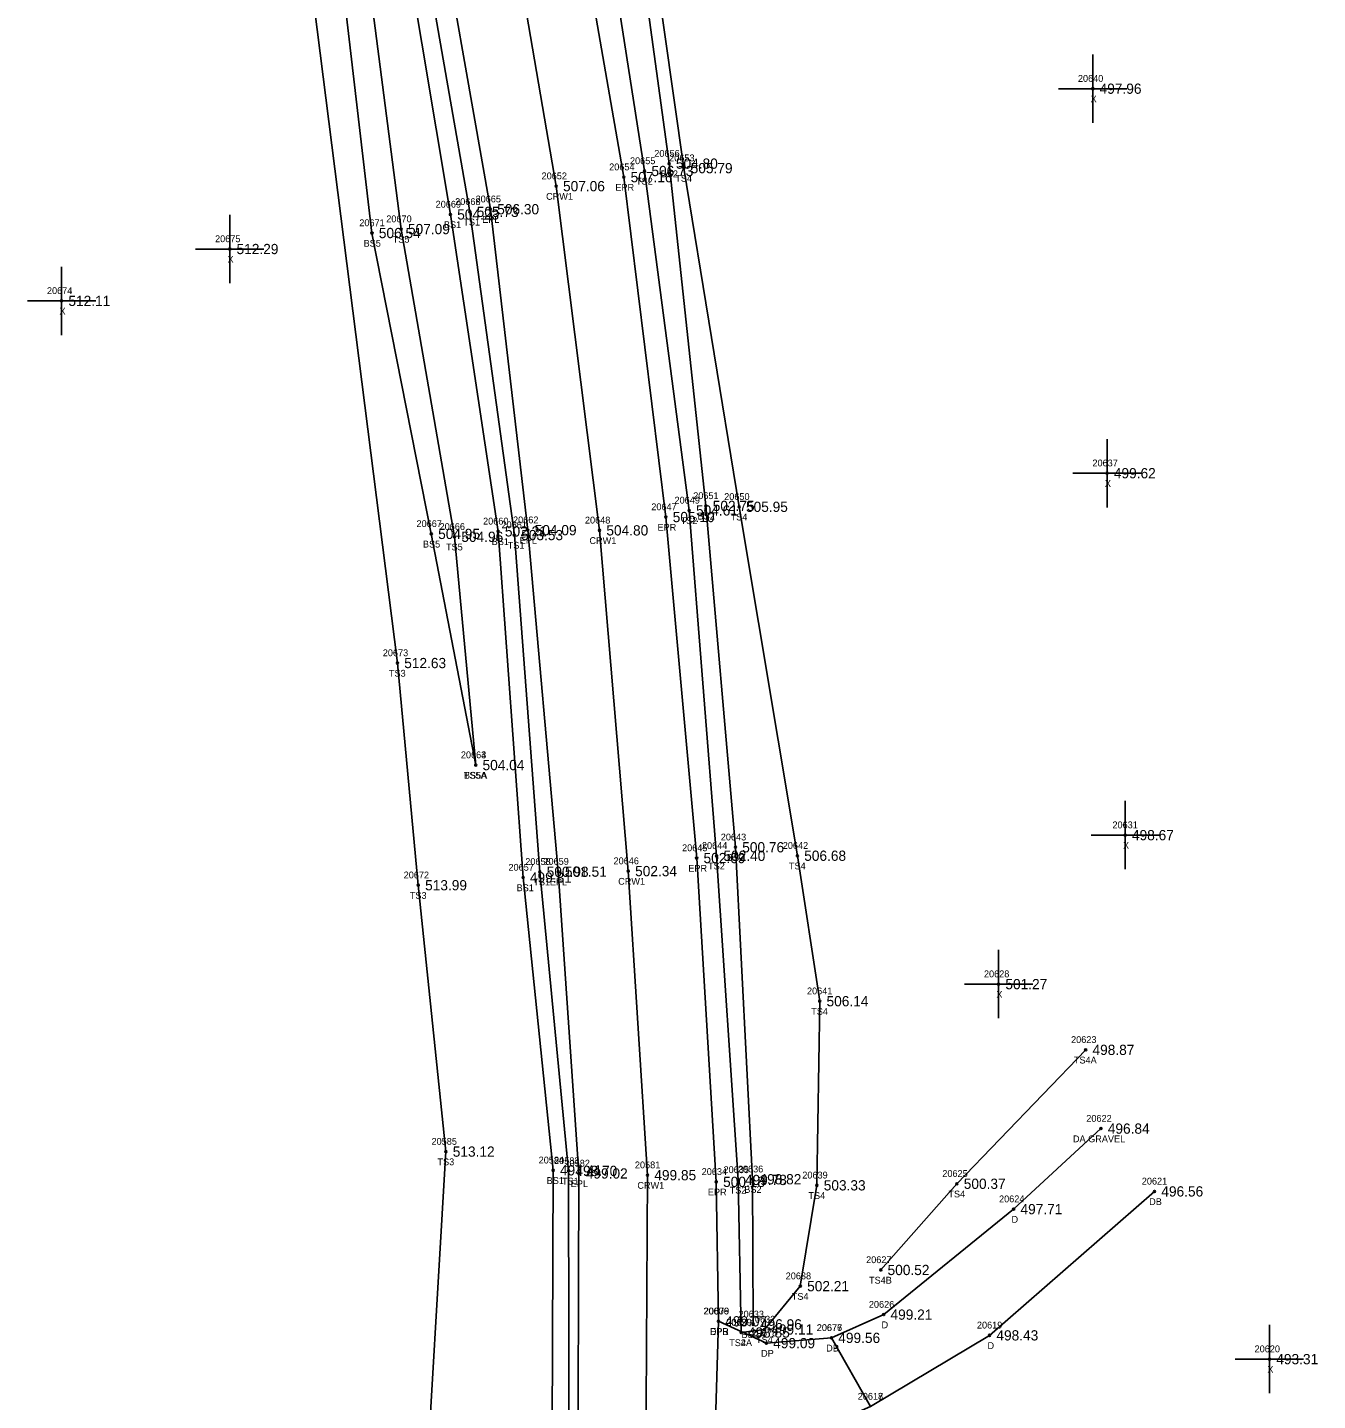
# Model space of a CAD drawing. Extents: x 1649406 to 1650436, y 896752 to 898178.
# Drawn here: x 1649854.4 to 1650043.4, y 897780.3 to 897981.4 of the extents above; entities that cross this region are included whole.
import ezdxf

# ---------------------------------------------------------------- set-up
doc = ezdxf.new("R2010")
doc.units = 0
for name, color, linetype in [('RD_DTM_BkLn1', 7, 'Continuous'), ('RD_DTM_BkLn2', 7, 'Continuous'), ('RD_DTM_BkLn_txCode', 7, 'Continuous'), ('RD_EX_Driveway', 7, 'Continuous'), ('RD_EX_Driveway_txCode', 7, 'Continuous'), ('RD_EX_Misc', 7, 'Continuous'), ('RD_EX_Misc_txCode', 7, 'Continuous'), ('RD_EX_Road', 7, 'Continuous'), ('RD_EX_Road_txCode', 7, 'Continuous'), ('RD_EX_TX_Driveway_ELEV', 7, 'Continuous'), ('RD_EX_TX_Misc_ELEV', 7, 'Continuous'), ('RD_EX_TX_Road_ELEV', 7, 'Continuous'), ('RD_HC_Survey_ELEV', 7, 'Continuous'), ('RD_HC_Survey_txCode', 7, 'Continuous'), ('RD_SMD_Locator', 7, 'Continuous')]:
    doc.layers.add(name, color=color, linetype=linetype)

msp = doc.modelspace()

# ---------------------------------------------------------------- linework, layer by layer
at = {"layer": 'RD_DTM_BkLn1'}
msp.add_lwpolyline([(1649894.9, 897462.66), (1649908.82, 897514.7), (1649920.62, 897564.87), (1649930.21, 897614.13), (1649937.18, 897663.59), (1649942.29, 897713.83), (1649944.94, 897762.9), (1649945.25, 897813.29), (1649942.44, 897857.84), (1649938.23, 897907.76), (1649931.88, 897958.19), (1649923.51, 898006.94), (1649914.47, 898059.31), (1649904.54, 898110.23), (1649895.09, 898157.93)], dxfattribs=at)
at = {"layer": 'RD_DTM_BkLn2'}
for points in [[(1649960.73, 897791.43), (1649960.66, 897812.69), (1649958.13, 897861.33), (1649953.81, 897911.34), (1649948.42, 897961.49), (1649941.65, 898011.04), (1649931.14, 898062.52), (1649921.88, 898114.25), (1649913.27, 898162.17)], [(1649958.96, 897790.24), (1649962.39, 897790.68), (1649967.64, 897797.03), (1649970.07, 897811.8), (1649970.48, 897838.78), (1649967.21, 897860.09), (1649958.68, 897911.21), (1649950.58, 897960.83), (1649943.4, 898011.37), (1649933.69, 898063.19), (1649926.67, 898115.06), (1649916.83, 898162.27)], [(1649958.96, 897790.24), (1649958.53, 897812.59), (1649955.38, 897860.08), (1649951.36, 897910.68), (1649944.83, 897960.41), (1649937.13, 898009.63), (1649927.84, 898061.63), (1649917.14, 898113.1), (1649909.51, 898160.93)], [(1649920.87, 897644.21), (1649923.9, 897665.21), (1649928.63, 897702.34), (1649930.33, 897715.28), (1649933.79, 897763.23), (1649933.69, 897813.91), (1649929.49, 897857.74), (1649925.75, 897907.07), (1649919.24, 897954.42), (1649910.51, 898004.53), (1649900.99, 898055.57), (1649897.4, 898076.37), (1649890.54, 898075.59)], [(1649920.09, 897873.37), (1649916.99, 897906.82), (1649909.17, 897951.9), (1649902.46, 898003.64), (1649895.01, 898054.19), (1649890.54, 898075.59)], [(1649902.31, 897569.09), (1649911.24, 897617.29), (1649920.65, 897666.08), (1649926.58, 897702.16), (1649928.32, 897715.46), (1649931.24, 897763.41), (1649931.43, 897814), (1649927.03, 897856.89), (1649923.37, 897907.61), (1649916.38, 897954.04), (1649907.99, 898004.31), (1649897.74, 898054.92), (1649893.88, 898075.41)], [(1649920.09, 897873.37), (1649913.59, 897907.24), (1649904.9, 897951.32), (1649898.8, 898003.15), (1649890.21, 898053.37), (1649884.63, 898071.42)], [(1649868.11, 897593.32), (1649891.92, 897625.99), (1649904.5, 897665.19), (1649913.68, 897716.44), (1649912.45, 897760.99), (1649915.73, 897816.74), (1649911.68, 897855.77), (1649908.62, 897888.32), (1649894.21, 898001.99), (1649884.42, 898052.27), (1649879.49, 898066.69)], [(1650009.44, 897831.65), (1649990.58, 897812.03), (1649979.42, 897799.4)]]:
    msp.add_lwpolyline(points, dxfattribs=at)
at = {"layer": 'RD_EX_Driveway'}
for points in [[(1650011.68, 897820.11), (1649998.89, 897808.31), (1649979.85, 897792.86), (1649972.2, 897789.45)], [(1649977.91, 897779.39), (1649995.36, 897789.82), (1650019.52, 897810.91)], [(1649954.77, 897762.63), (1649957.88, 897765.34), (1649960.78, 897770.05), (1649964.93, 897773.68), (1649977.91, 897779.39), (1649972.2, 897789.45), (1649962.67, 897788.68), (1649955.64, 897791.88)]]:
    msp.add_lwpolyline(points, dxfattribs=at)
at = {"layer": 'RD_EX_Misc'}
for p, q in [((1650010.48, 897967.47), (1650010.48, 897977.47)), ((1650005.48, 897972.47), (1650015.48, 897972.47)), ((1649884.06, 897943.98), (1649884.06, 897953.98)), ((1649879.06, 897948.98), (1649889.06, 897948.98)), ((1649859.43, 897936.38), (1649859.43, 897946.38)), ((1649854.43, 897941.38), (1649864.43, 897941.38)), ((1650012.57, 897911.13), (1650012.57, 897921.13)), ((1650007.57, 897916.13), (1650017.57, 897916.13)), ((1650015.22, 897858.11), (1650015.22, 897868.11)), ((1650010.22, 897863.11), (1650020.22, 897863.11)), ((1649996.68, 897836.28), (1649996.68, 897846.28)), ((1649991.68, 897841.28), (1650001.68, 897841.28)), ((1650036.36, 897781.34), (1650036.36, 897791.34)), ((1650031.36, 897786.34), (1650041.36, 897786.34))]:
    msp.add_line(p, q, dxfattribs=at)
at = {"layer": 'RD_EX_Road'}
for points in [[(1649905.13, 897459.2), (1649918.81, 897511.88), (1649930.39, 897563.05), (1649939.7, 897612.37), (1649946.83, 897662.25), (1649952.14, 897712.87), (1649954.77, 897762.63), (1649955.64, 897791.88), (1649955.33, 897812.31), (1649952.46, 897859.75), (1649947.95, 897909.71), (1649941.78, 897959.51), (1649933.15, 898009.23), (1649924.03, 898060.85), (1649913.91, 898112.48), (1649904.76, 898159.93)], [(1649885.84, 897465.29), (1649899.42, 897516.76), (1649910.69, 897567.43), (1649919.68, 897616.11), (1649926.54, 897664.67), (1649931.97, 897714.33), (1649935.04, 897763.32), (1649935.22, 897813.54), (1649932.16, 897857.76), (1649927.73, 897907.79), (1649922.24, 897954.81), (1649913.41, 898005.06), (1649903.99, 898056.19), (1649899.68, 898079.2), (1649896.48, 898096.53), (1649894.5, 898108.47), (1649884.77, 898155.82)]]:
    msp.add_lwpolyline(points, dxfattribs=at)
at = {"layer": 'RD_SMD_Locator'}
for centre in [(1650010.48, 897972.47), (1649948.42, 897961.49), (1649950.58, 897960.83), (1649941.78, 897959.51), (1649944.83, 897960.41), (1649931.88, 897958.19), (1649922.24, 897954.81), (1649916.38, 897954.04), (1649919.24, 897954.42), (1649904.9, 897951.32), (1649909.17, 897951.9), (1649884.06, 897948.98), (1649859.43, 897941.38), (1650012.57, 897916.13), (1649951.36, 897910.68), (1649953.81, 897911.34), (1649958.68, 897911.21), (1649947.95, 897909.71), (1649913.59, 897907.24), (1649916.99, 897906.82), (1649923.37, 897907.61), (1649925.75, 897907.07), (1649927.73, 897907.79), (1649938.23, 897907.76), (1649908.62, 897888.32), (1649920.09, 897873.37), (1649920.09, 897873.37), (1650015.22, 897863.11), (1649958.13, 897861.33), (1649952.46, 897859.75), (1649955.38, 897860.08), (1649967.21, 897860.09), (1649927.03, 897856.89), (1649929.49, 897857.74), (1649932.16, 897857.76), (1649942.44, 897857.84), (1649911.68, 897855.77), (1649996.68, 897841.28), (1649970.48, 897838.78), (1650009.44, 897831.65), (1650011.68, 897820.11), (1649915.73, 897816.74), (1649931.43, 897814), (1649933.69, 897813.91), (1649935.22, 897813.54), (1649945.25, 897813.29), (1649955.33, 897812.31), (1649958.53, 897812.59), (1649960.66, 897812.69), (1649990.58, 897812.03), (1649970.07, 897811.8), (1650019.52, 897810.91), (1649998.89, 897808.31), (1649979.42, 897799.4), (1649967.64, 897797.03), (1649955.64, 897791.88), (1649955.64, 897791.88), (1649979.85, 897792.86), (1649958.96, 897790.24), (1649958.96, 897790.24), (1649960.73, 897791.43), (1649962.39, 897790.68), (1649962.67, 897788.68), (1649972.2, 897789.45), (1649972.2, 897789.45), (1649995.36, 897789.82), (1650036.36, 897786.34)]:
    msp.add_circle(centre, 0.15, dxfattribs=at)

# ---------------------------------------------------------------- texts
at = {"layer": 'RD_DTM_BkLn_txCode'}
for s, p in [('20656', (1649946.25, 897962.49)), ('20655', (1649942.69, 897961.41)), ('20653', (1649948.43, 897961.83)), ('TS2', (1649943.58, 897958.41)), ('BS2', (1649947.19, 897959.49)), ('TS4', (1649949.33, 897958.83)), ('20669', (1649914.22, 897955.04)), ('20668', (1649917.08, 897955.42)), ('20671', (1649903.04, 897952.32)), ('20670', (1649906.99, 897952.9)), ('BS1', (1649915.44, 897952.04)), ('TS1', (1649918.28, 897952.42)), ('BS5', (1649903.67, 897949.32)), ('TS5', (1649907.93, 897949.9)), ('20651', (1649951.95, 897912.34)), ('20650', (1649956.49, 897912.21)), ('20649', (1649949.21, 897911.68)), ('20667', (1649911.42, 897908.24)), ('20666', (1649914.8, 897907.82)), ('20660', (1649921.17, 897908.61)), ('20661', (1649923.87, 897908.07)), ('TS2', (1649950.11, 897908.68)), ('BS2', (1649952.58, 897909.34)), ('TS4', (1649957.43, 897909.21)), ('BS5', (1649912.36, 897905.24)), ('TS5', (1649915.74, 897904.82)), ('BS1', (1649922.43, 897905.61)), ('TS1', (1649924.79, 897905.07)), ('20673', (1649906.48, 897889.32)), ('TS3', (1649907.38, 897886.32)), ('20663', (1649917.92, 897874.37)), ('20664', (1649917.92, 897874.37)), ('TS5A', (1649918.35, 897871.37)), ('BS5A', (1649918.37, 897871.37)), ('20643', (1649955.99, 897862.33)), ('20644', (1649953.23, 897861.08)), ('20642', (1649965.07, 897861.09)), ('20657', (1649924.89, 897857.89)), ('20658', (1649927.35, 897858.74)), ('TS2', (1649954.13, 897858.08)), ('BS2', (1649956.9, 897859.33)), ('TS4', (1649965.97, 897858.09)), ('20672', (1649909.54, 897856.77)), ('TS1', (1649928.53, 897855.74)), ('TS3', (1649910.44, 897853.77)), ('BS1', (1649926.08, 897854.89)), ('20641', (1649968.62, 897839.78)), ('TS4', (1649969.24, 897836.78)), ('20623', (1650007.3, 897832.65)), ('TS4A', (1650007.71, 897829.65)), ('20585', (1649913.62, 897817.74)), ('TS3', (1649914.49, 897814.74)), ('20584', (1649929.31, 897815)), ('20583', (1649931.57, 897814.91)), ('20635', (1649956.39, 897813.59)), ('20636', (1649958.49, 897813.69)), ('BS1', (1649930.48, 897812)), ('TS1', (1649932.73, 897811.91)), ('20639', (1649967.93, 897812.8)), ('20625', (1649988.44, 897813.03)), ('TS2', (1649957.29, 897810.59)), ('BS2', (1649959.43, 897810.69)), ('TS4', (1649968.83, 897809.8)), ('TS4', (1649989.33, 897810.03)), ('20627', (1649977.28, 897800.4)), ('20638', (1649965.5, 897798.03)), ('TS4B', (1649977.7, 897797.4)), ('TS4', (1649966.39, 897795.03)), ('20630', (1649956.78, 897791.24)), ('20629', (1649956.82, 897791.24)), ('20633', (1649958.59, 897792.43)), ('20632', (1649960.25, 897791.68)), ('BS2A', (1649959.02, 897789.43)), ('TS2A', (1649957.22, 897788.24)), ('TS4A', (1649957.22, 897788.24)), ('TS4', (1649961.15, 897788.68))]:
    msp.add_text(s, height=1, dxfattribs=at).set_placement(p)
at = {"layer": 'RD_EX_Driveway_txCode'}
for s, p in [('20622', (1650009.53, 897821.11)), ('DA GRAVEL', (1650007.57, 897818.11)), ('20621', (1650017.66, 897811.91)), ('20624', (1649996.75, 897809.31)), ('DB', (1650018.74, 897808.91)), ('D', (1649998.58, 897806.31)), ('20626', (1649977.68, 897793.86)), ('20679', (1649953.5, 897792.88)), ('DPB', (1649954.39, 897789.88)), ('20678', (1649960.53, 897789.68)), ('20676', (1649970.04, 897790.45)), ('20677', (1649970.06, 897790.45)), ('D', (1649979.54, 897790.86)), ('20619', (1649993.51, 897790.82)), ('DB', (1649971.43, 897787.45)), ('DP', (1649971.43, 897787.45)), ('D', (1649995.06, 897787.82)), ('DP', (1649961.89, 897786.68)), ('20617', (1649976.05, 897780.39)), ('20618', (1649976.05, 897780.39))]:
    msp.add_text(s, height=1, dxfattribs=at).set_placement(p)
at = {"layer": 'RD_EX_Misc_txCode'}
for s, p in [('20640', (1650008.3, 897973.47)), ('X', (1650010.16, 897970.47)), ('20675', (1649881.91, 897949.98)), ('X', (1649883.74, 897946.98)), ('20674', (1649857.29, 897942.38)), ('X', (1649859.12, 897939.38)), ('20637', (1650010.43, 897917.13)), ('X', (1650012.25, 897914.13)), ('20631', (1650013.36, 897864.11)), ('X', (1650014.91, 897861.11)), ('20628', (1649994.54, 897842.28)), ('X', (1649996.36, 897839.28)), ('20620', (1650034.18, 897787.34)), ('X', (1650036.05, 897784.34))]:
    msp.add_text(s, height=1, dxfattribs=at).set_placement(p)
at = {"layer": 'RD_EX_Road_txCode'}
for s, p in [('20654', (1649939.64, 897960.51)), ('EPR', (1649940.55, 897957.51)), ('20665', (1649920.07, 897955.81)), ('EPL', (1649921.04, 897952.81)), ('20647', (1649945.81, 897910.71)), ('20662', (1649925.56, 897908.79)), ('EPR', (1649946.72, 897907.71)), ('EPL', (1649926.53, 897905.79)), ('20645', (1649950.32, 897860.75)), ('20659', (1649930.01, 897858.76)), ('EPR', (1649951.23, 897857.75)), ('EPL', (1649930.95, 897855.76)), ('20582', (1649933.1, 897814.54)), ('20634', (1649953.19, 897813.31)), ('EPL', (1649934.01, 897811.54)), ('EPR', (1649954.1, 897810.31)), ('20606', (1649953.44, 897792.88)), ('EPR', (1649954.41, 897789.88))]:
    msp.add_text(s, height=1, dxfattribs=at).set_placement(p)
at = {"layer": 'RD_EX_TX_Driveway_ELEV'}
for s, p in [('496.84', (1650012.68, 897819.36)), ('496.56', (1650020.52, 897810.16)), ('497.71', (1649999.89, 897807.56)), ('499.07', (1649956.64, 897791.13)), ('499.21', (1649980.85, 897792.11)), ('499.56', (1649973.2, 897788.7)), ('499.56', (1649973.2, 897788.7)), ('498.43', (1649996.36, 897789.07)), ('499.09', (1649963.67, 897787.93))]:
    msp.add_text(s, height=1.5, dxfattribs=at).set_placement(p)
at = {"layer": 'RD_EX_TX_Misc_ELEV'}
for s, p in [('497.96', (1650011.48, 897971.72)), ('506.73', (1649945.83, 897959.66)), ('504.80', (1649949.42, 897960.74)), ('505.79', (1649951.58, 897960.08)), ('505.73', (1649920.24, 897953.67)), ('504.23', (1649917.38, 897953.29)), ('506.54', (1649905.9, 897950.57)), ('507.09', (1649910.17, 897951.15)), ('512.29', (1649885.06, 897948.23)), ('512.11', (1649860.43, 897940.63)), ('499.62', (1650013.57, 897915.38)), ('504.61', (1649952.36, 897909.93)), ('502.75', (1649954.81, 897910.59)), ('505.95', (1649959.68, 897910.46)), ('504.95', (1649914.59, 897906.49)), ('504.96', (1649917.99, 897906.07)), ('502.21', (1649924.37, 897906.86)), ('503.53', (1649926.75, 897906.32)), ('512.63', (1649909.62, 897887.57)), ('504.04', (1649921.09, 897872.62)), ('504.04', (1649921.09, 897872.62)), ('498.67', (1650016.22, 897862.36)), ('502.40', (1649956.38, 897859.33)), ('500.76', (1649959.13, 897860.58)), ('506.68', (1649968.21, 897859.34)), ('500.98', (1649930.49, 897856.99)), ('513.99', (1649912.68, 897855.02)), ('499.31', (1649928.03, 897856.14)), ('501.27', (1649997.68, 897840.53)), ('506.14', (1649971.48, 897838.03)), ('498.87', (1650010.44, 897830.9)), ('513.12', (1649916.73, 897815.99)), ('497.41', (1649932.43, 897813.25)), ('498.70', (1649934.69, 897813.16)), ('499.78', (1649959.53, 897811.84)), ('498.82', (1649961.66, 897811.94)), ('503.33', (1649971.07, 897811.05)), ('500.37', (1649991.58, 897811.28)), ('500.52', (1649980.42, 897798.65)), ('502.21', (1649968.64, 897796.28)), ('496.96', (1649961.73, 897790.68)), ('498.85', (1649959.96, 897789.49)), ('498.85', (1649959.96, 897789.49)), ('499.11', (1649963.39, 897789.93)), ('493.31', (1650037.36, 897785.59))]:
    msp.add_text(s, height=1.5, dxfattribs=at).set_placement(p)
at = {"layer": 'RD_EX_TX_Road_ELEV'}
for s, p in [('507.16', (1649942.78, 897958.76)), ('506.30', (1649923.24, 897954.06)), ('505.10', (1649948.95, 897908.96)), ('504.09', (1649928.73, 897907.04)), ('502.69', (1649953.46, 897859)), ('501.51', (1649933.16, 897857.01)), ('499.02', (1649936.22, 897812.79)), ('500.18', (1649956.33, 897811.56)), ('499.07', (1649956.64, 897791.13))]:
    msp.add_text(s, height=1.5, dxfattribs=at).set_placement(p)
at = {"layer": 'RD_HC_Survey_ELEV'}
for s, p in [('507.06', (1649932.88, 897957.44)), ('504.80', (1649939.23, 897907.01)), ('502.34', (1649943.44, 897857.09)), ('499.85', (1649946.25, 897812.54))]:
    msp.add_text(s, height=1.5, dxfattribs=at).set_placement(p)
at = {"layer": 'RD_HC_Survey_txCode'}
for s, p in [('20652', (1649929.74, 897959.19)), ('CRW1', (1649930.4, 897956.19)), ('20648', (1649936.09, 897908.76)), ('CRW1', (1649936.75, 897905.76)), ('20646', (1649940.28, 897858.84)), ('CRW1', (1649940.96, 897855.84)), ('20581', (1649943.41, 897814.29)), ('CRW1', (1649943.77, 897811.29))]:
    msp.add_text(s, height=1, dxfattribs=at).set_placement(p)

doc.saveas('drawing.dxf')
